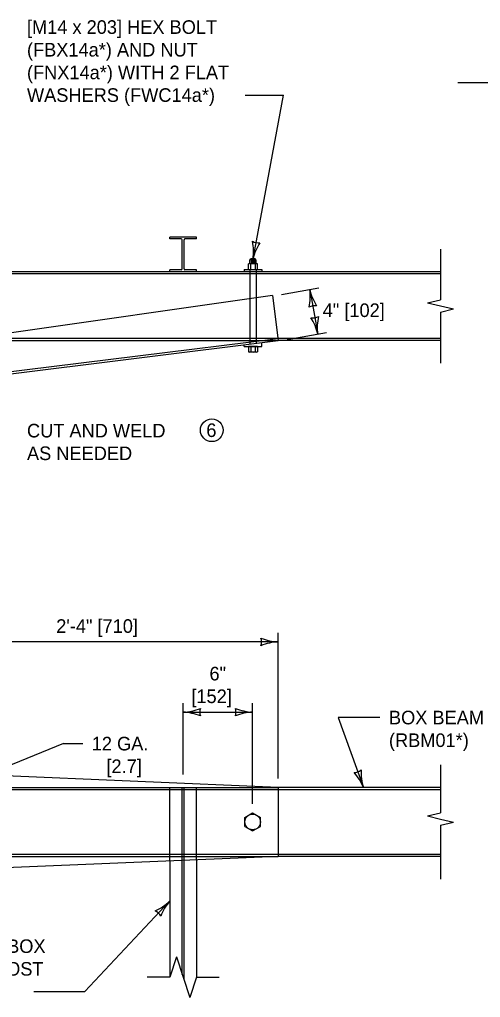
# Model space of a CAD drawing. Extents: x 49991.4 to 50021, y 49987.6 to 50011.4.
# Drawn here: x 50003.426 to 50005.459, y 49990.624 to 49994.938 of the extents above; entities that cross this region are included whole.
import ezdxf

# ---------------------------------------------------------------- set-up
doc = ezdxf.new("R2010")
doc.units = 0
for name, color, linetype in [('Level 1', 7, 'Continuous'), ('Level 2', 7, 'Continuous'), ('Level 3', 7, 'Continuous'), ('Level 4', 7, 'Continuous'), ('Level 6', 7, 'Continuous')]:
    doc.layers.add(name, color=color, linetype=linetype)

msp = doc.modelspace()

# ---------------------------------------------------------------- linework, layer by layer
at = {"layer": 'Level 1'}
for p, q in [((50005.7204, 49994.6584), (50005.3597, 49994.6584)), ((50004.2069, 49993.9782), (50004.0885, 49993.9782)), ((50004.0885, 49993.9702), (50004.0885, 49993.9782)), ((50004.1397, 49993.9702), (50004.0885, 49993.9702)), ((50004.1437, 49993.8379), (50004.1437, 49993.9662)), ((50004.1517, 49993.8379), (50004.1517, 49993.9662)), ((50004.2069, 49993.9702), (50004.1557, 49993.9702)), ((50004.2069, 49993.9702), (50004.2069, 49993.9782)), ((50004.4359, 49993.8367), (50004.4359, 49993.8605)), ((50004.4709, 49993.8613), (50004.441, 49993.8613)), ((50004.4419, 49993.8771), (50004.4469, 49993.8821)), ((50004.4419, 49993.8613), (50004.4419, 49993.8771)), ((50004.4459, 49993.8366), (50004.4459, 49993.8605)), ((50004.4649, 49993.8821), (50004.4469, 49993.8821)), ((50004.4649, 49993.8781), (50004.4469, 49993.8781)), ((50004.4649, 49993.8741), (50004.4469, 49993.8741)), ((50004.4649, 49993.8701), (50004.4469, 49993.8701)), ((50004.4649, 49993.8661), (50004.4469, 49993.8661)), ((50004.4699, 49993.8771), (50004.4649, 49993.8821)), ((50004.466, 49993.8605), (50004.466, 49993.8366)), ((50004.4699, 49993.8613), (50004.4699, 49993.8771)), ((50004.4759, 49993.8367), (50004.4759, 49993.8605)), ((50005.2826, 49993.8259), (50000.9808, 49993.8259)), ((50004.1397, 49993.8339), (50004.0885, 49993.8339)), ((50004.0885, 49993.8259), (50004.0885, 49993.8339)), ((50004.2069, 49993.8339), (50004.1557, 49993.8339)), ((50004.2069, 49993.8259), (50004.2069, 49993.8339)), ((50004.506, 49993.8259), (50004.4058, 49993.8259)), ((50004.4168, 49993.8358), (50004.495, 49993.8358)), ((50004.4168, 49993.8358), (50004.4168, 49993.8259)), ((50004.495, 49993.8358), (50004.495, 49993.8259)), ((50004.5422, 49993.7204), (50003.1472, 49993.5219)), ((50004.5422, 49993.7204), (50004.5672, 49993.5219)), ((50003.1472, 49993.3459), (50004.5672, 49993.5219)), ((50005.2826, 49993.5219), (50004.5672, 49993.5219)), ((50004.4168, 49993.4961), (50004.4168, 49993.5032)), ((50004.4168, 49993.4961), (50004.495, 49993.4961)), ((50004.4359, 49993.4953), (50004.4359, 49993.4722)), ((50004.4709, 49993.4714), (50004.441, 49993.4714)), ((50004.4458, 49993.4953), (50004.4458, 49993.4722)), ((50004.466, 49993.4953), (50004.466, 49993.4722)), ((50004.4759, 49993.4953), (50004.4759, 49993.4722)), ((50004.495, 49993.4961), (50004.495, 49993.5129)), ((50004.5668, 49991.5504), (50003.1472, 49991.6104)), ((50004.5668, 49991.5504), (50004.5668, 49991.2464)), ((50005.2826, 49991.5504), (50004.5668, 49991.5504)), ((50004.4199, 49991.4181), (50004.4542, 49991.438)), ((50004.4199, 49991.3785), (50004.4199, 49991.4181)), ((50004.4542, 49991.438), (50004.4886, 49991.4181)), ((50004.4886, 49991.3785), (50004.4886, 49991.4181)), ((50004.4199, 49991.3785), (50004.4542, 49991.3587)), ((50004.4542, 49991.3587), (50004.4886, 49991.3785)), ((50004.5668, 49991.2464), (50003.1472, 49991.1864)), ((50004.2069, 49991.2311), (50004.2069, 49990.7137)), ((50005.2826, 49991.2464), (50004.5668, 49991.2464)), ((50004.0889, 49991.2262), (50004.0889, 49990.7137))]:
    msp.add_line(p, q, dxfattribs=at)
msp.add_circle((50004.4542, 49991.3983), 0.0344, dxfattribs=at)
for centre, start, end in [((50004.1397, 49993.9662), 0, 90), ((50004.1557, 49993.9662), 90, 180), ((50004.1397, 49993.8379), 270, 0), ((50004.1557, 49993.8379), 180, 270)]:
    msp.add_arc(centre, 0.004, start, end, dxfattribs=at)
for centre, major_axis, start_param, end_param in [((50004.4409, 49993.8551), (-0.01, 0), 4.198439, 5.235988), ((50004.4559, 49993.8363), (-0.04, 0), 4.457545, 4.967234), ((50004.4709, 49993.8551), (-0.01, 0), 4.188789, 5.226338), ((50004.441, 49993.842), (-0.00997, 0), 1.04339, 2.084746), ((50004.4559, 49993.8607), (-0.0399, 0), 1.31595, 1.825641), ((50004.4709, 49993.842), (-0.00997, 0), 1.056847, 2.102179), ((50004.4409, 49993.4899), (-0.01, 0), 4.198439, 5.235988), ((50004.4409, 49993.4776), (-0.01, 0), 1.047198, 2.084746), ((50004.4559, 49993.4712), (-0.04, 0), 4.457545, 4.967235), ((50004.4559, 49993.4964), (-0.04, 0), 1.315951, 1.825641), ((50004.4709, 49993.4899), (-0.01, 0), 4.188789, 5.226338), ((50004.4709, 49993.4776), (-0.01, 0), 1.056847, 2.094396)]:
    msp.add_ellipse(centre, major_axis=major_axis, ratio=0.623816, start_param=start_param, end_param=end_param, dxfattribs=at)
at = {"layer": 'Level 2'}
msp.add_circle((50004.2741, 49993.1265), 0.0503, dxfattribs=at)
at = {"layer": 'Level 3'}
for p, q in [((50004.4213, 49994.6051), (50004.5906, 49994.6051)), ((50004.4559, 49993.8821), (50004.5906, 49994.6051)), ((50004.5819, 49993.7253), (50004.7457, 49993.7544)), ((50004.7063, 49993.7474), (50004.7411, 49993.5506)), ((50004.6069, 49993.5268), (50004.7805, 49993.5576)), ((50004.5668, 49991.5904), (50004.5668, 49992.2326)), ((50004.5668, 49992.1926), (50003.1472, 49992.1926)), ((50004.1479, 49991.6081), (50004.1479, 49991.9227)), ((50004.4542, 49991.478), (50004.4542, 49991.9227)), ((50004.1479, 49991.8827), (50004.4542, 49991.8827)), ((50005.0153, 49991.859), (50004.8313, 49991.859)), ((50004.8313, 49991.859), (50004.9428, 49991.5504)), ((50003.6208, 49991.7439), (50003.2784, 49991.6048)), ((50003.6208, 49991.7439), (50003.7047, 49991.7439)), ((50004.0889, 49991.0497), (50003.7149, 49990.6503)), ((50003.4896, 49990.6503), (50003.7149, 49990.6503))]:
    msp.add_line(p, q, dxfattribs=at)
for centre, radius, start, end in [((50004.2359, 49993.9138), 0.2223, 351.8117, 11.9952), ((50004.4794, 49994.0082), 0.0548, 241.59, 277.3124), ((50004.6826, 49993.8282), 0.233, 147.3741, 166.6239), ((50004.4751, 49993.7182), 0.233, 347.9531, 7.2029), ((50004.9234, 49993.7951), 0.2223, 192.3907, 212.5742), ((50004.7286, 49993.6211), 0.0548, 82.169, 117.8914), ((50004.7188, 49993.6768), 0.0548, 262.169, 297.8914), ((50004.5239, 49993.5029), 0.2223, 12.3907, 32.5742), ((50004.9722, 49993.5798), 0.233, 167.9531, 187.2029), ((50004.4386, 49992.1926), 0.0548, 342.1388, 17.8612), ((50004.5783, 49992.4253), 0.233, 247.9228, 267.1727), ((50004.5759, 49991.9705), 0.2223, 92.3605, 112.544), ((50004.1387, 49992.1048), 0.2223, 272.3605, 292.544), ((50004.1364, 49991.65), 0.233, 67.9228, 87.1727), ((50004.2761, 49991.8827), 0.0548, 162.1388, 197.8612), ((50004.326, 49991.8827), 0.0548, 342.1388, 17.8612), ((50004.4657, 49992.1154), 0.233, 247.9228, 267.1727), ((50004.4634, 49991.6606), 0.2223, 92.3605, 112.544), ((50004.8993, 49991.6709), 0.0548, 272.0143, 307.7367), ((50004.7371, 49991.4662), 0.2223, 22.236, 42.4195), ((50005.1656, 49991.6187), 0.233, 177.7984, 197.0482), ((50003.9268, 49991.2172), 0.233, 294.8072, 314.0571), ((50004.2573, 49990.9046), 0.2223, 139.2448, 159.4284), ((50004.0012, 49990.9561), 0.0548, 29.0232, 64.7455)]:
    msp.add_arc(centre, radius, start, end, dxfattribs=at)
at = {"layer": 'Level 4'}
for p, q in [((50005.2826, 49993.8163), (50000.9808, 49993.8163)), ((50004.4419, 49993.8358), (50004.4419, 49993.5063)), ((50004.4699, 49993.8358), (50004.4699, 49993.5098)), ((50005.2826, 49993.5315), (50000.9808, 49993.5315)), ((50002.9414, 49993.5219), (50004.5672, 49993.5219)), ((50003.1467, 49993.355), (50004.5661, 49993.5309)), ((50000.9808, 49991.5504), (50004.5668, 49991.5504)), ((50000.9808, 49991.5408), (50005.2826, 49991.5408)), ((50004.0889, 49991.2262), (50004.0889, 49991.5504)), ((50004.1439, 49990.7258), (50004.1439, 49991.5504)), ((50004.1519, 49990.7016), (50004.1519, 49991.5504)), ((50004.2069, 49991.2311), (50004.2069, 49991.5504)), ((50000.9808, 49991.256), (50005.2826, 49991.256)), ((50000.9808, 49991.2464), (50004.5668, 49991.2464))]:
    msp.add_line(p, q, dxfattribs=at)
at = {"layer": 'Level 6'}
for p, q in [((50005.2826, 49993.9259), (50005.2826, 49993.7018)), ((50005.2259, 49993.6886), (50005.2826, 49993.7018)), ((50005.2259, 49993.6886), (50005.2826, 49993.675)), ((50005.2826, 49993.675), (50005.3396, 49993.6616)), ((50005.2826, 49993.648), (50005.3396, 49993.6616)), ((50005.2826, 49993.648), (50005.2826, 49993.4219)), ((50005.2826, 49991.6504), (50005.2826, 49991.4379)), ((50005.2259, 49991.4247), (50005.2826, 49991.4379)), ((50005.2259, 49991.4247), (50005.2826, 49991.4111)), ((50005.2826, 49991.4111), (50005.3396, 49991.3977)), ((50005.2826, 49991.3841), (50005.3396, 49991.3977)), ((50005.2826, 49991.3841), (50005.2826, 49991.1464)), ((50004.1184, 49990.8033), (50004.0889, 49990.7137)), ((50004.1184, 49990.8033), (50004.1479, 49990.7137)), ((50004.0889, 49990.7137), (50003.9889, 49990.7137)), ((50004.1479, 49990.7137), (50004.1774, 49990.6241)), ((50004.2069, 49990.7137), (50004.1774, 49990.6241)), ((50004.2069, 49990.7137), (50004.3069, 49990.7137))]:
    msp.add_line(p, q, dxfattribs=at)

# ---------------------------------------------------------------- texts
at = {"layer": 'Level 2'}
for s, p in [('[M14 x 203] HEX BOLT', (50003.459, 49994.8751)), ('(FBX14a*) AND NUT', (50003.459, 49994.7751)), ('(FNX14a*) WITH 2 FLAT', (50003.459, 49994.6751)), ('WASHERS (FWC14a*)', (50003.459, 49994.5751)), ('12 GA.', (50003.7447, 49991.7139)), ('[2.7]', (50003.8093, 49991.6139))]:
    msp.add_text(s, height=0.06, rotation=360, dxfattribs=at).set_placement(p)
for s, p in [('4" [102]', (50004.7631, 49993.6259)), ('CUT AND WELD ', (50003.4591, 49993.0947)), ('6', (50004.2499, 49993.0966)), ('AS NEEDED', (50003.4591, 49992.9947)), ('2\'-4" [710]', (50003.588, 49992.2326)), ('6"', (50004.2638, 49992.0227)), ('[152]', (50004.1839, 49991.9227)), ('BOX BEAM RAIL', (50005.0553, 49991.829)), ('(RBM01*)', (50005.0553, 49991.729)), ('TYPE A BOX', (50003.0639, 49990.8203)), ('BEAM POST', (50003.0639, 49990.7203))]:
    msp.add_text(s, height=0.06, dxfattribs=at).set_placement(p)

doc.saveas('drawing.dxf')
